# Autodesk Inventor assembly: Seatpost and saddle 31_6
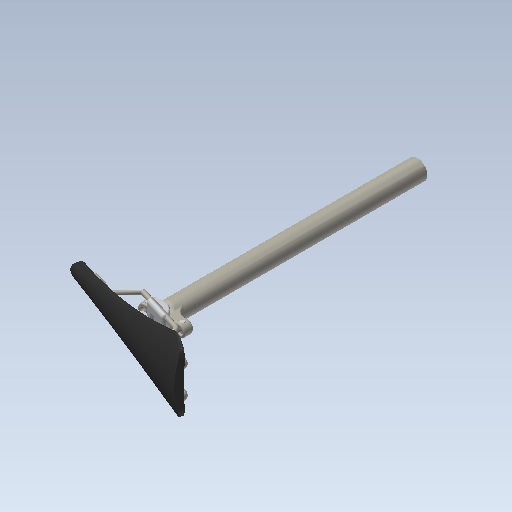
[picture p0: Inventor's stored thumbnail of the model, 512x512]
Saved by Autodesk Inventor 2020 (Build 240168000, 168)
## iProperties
Created: 2013-11
Part Number: Seatpost and saddle 31_6
Material: Ogólny
Document SubType Name: Assembly
Designer: Tomasz
Sending System: Autodesk Inventor 2012
Preprocessor: Autodesk Inventor 2012
Title: C:\Users\filip\Dropbox\FIETS\fietstekeningen\Seatpost and saddle 31_8.stp
Author: filip
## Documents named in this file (9)
- C:\Users\bruno\Documents\1-Cours-2020-21\1STI2D-2020-21\IT\6. Antivol\Inventor-Antivol\INVENTOR 2018_Steel Hardtail B+\Seatpost and saddle 31_6.iam
- C:\Users\bruno\Documents\1-Cours-2020-21\1STI2D-2020-21\IT\6. Antivol\Inventor-Antivol\INVENTOR 2018_Steel Hardtail B+\zadelpen.ipt
- C:\Users\bruno\Documents\1-Cours-2020-21\1STI2D-2020-21\IT\6. Antivol\Inventor-Antivol\INVENTOR 2018_Steel Hardtail B+\zadelpen - moer.ipt
- C:\Users\bruno\Documents\1-Cours-2020-21\1STI2D-2020-21\IT\6. Antivol\Inventor-Antivol\INVENTOR 2018_Steel Hardtail B+\zadelpen - steun.ipt
- C:\Users\bruno\Documents\1-Cours-2020-21\1STI2D-2020-21\IT\6. Antivol\Inventor-Antivol\INVENTOR 2018_Steel Hardtail B+\zadelpen - steun boven.ipt
- C:\Users\bruno\Documents\1-Cours-2020-21\1STI2D-2020-21\IT\6. Antivol\Inventor-Antivol\INVENTOR 2018_Steel Hardtail B+\zadel.ipt
- C:\Users\bruno\Documents\1-Cours-2020-21\1STI2D-2020-21\IT\6. Antivol\Inventor-Antivol\INVENTOR 2018_Steel Hardtail B+\zadelpen - moer lang.ipt
- C:\Users\bruno\Documents\1-Cours-2020-21\1STI2D-2020-21\IT\6. Antivol\Inventor-Antivol\INVENTOR 2018_Steel Hardtail B+\ISO 4762 - M5 x 35DIN EN ISO.ipt
- C:\Users\bruno\Documents\1-Cours-2020-21\1STI2D-2020-21\IT\6. Antivol\Inventor-Antivol\INVENTOR 2018_Steel Hardtail B+\DIN EN ISO 4762 M5 x 30.ipt
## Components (10 placed, 8 different names)
1. zadelpen:1
2. zadelpen - moer:1
3. zadelpen - steun:1
4. zadelpen - steun boven:1
5. zadelpen - moer:2
6. zadel:1
7. zadelpen - moer lang:1
8. zadelpen - moer lang:2
9. ISO 4762 - M5 x 35DIN EN ISO:1
10. DIN EN ISO 4762 M5 x 30:1
